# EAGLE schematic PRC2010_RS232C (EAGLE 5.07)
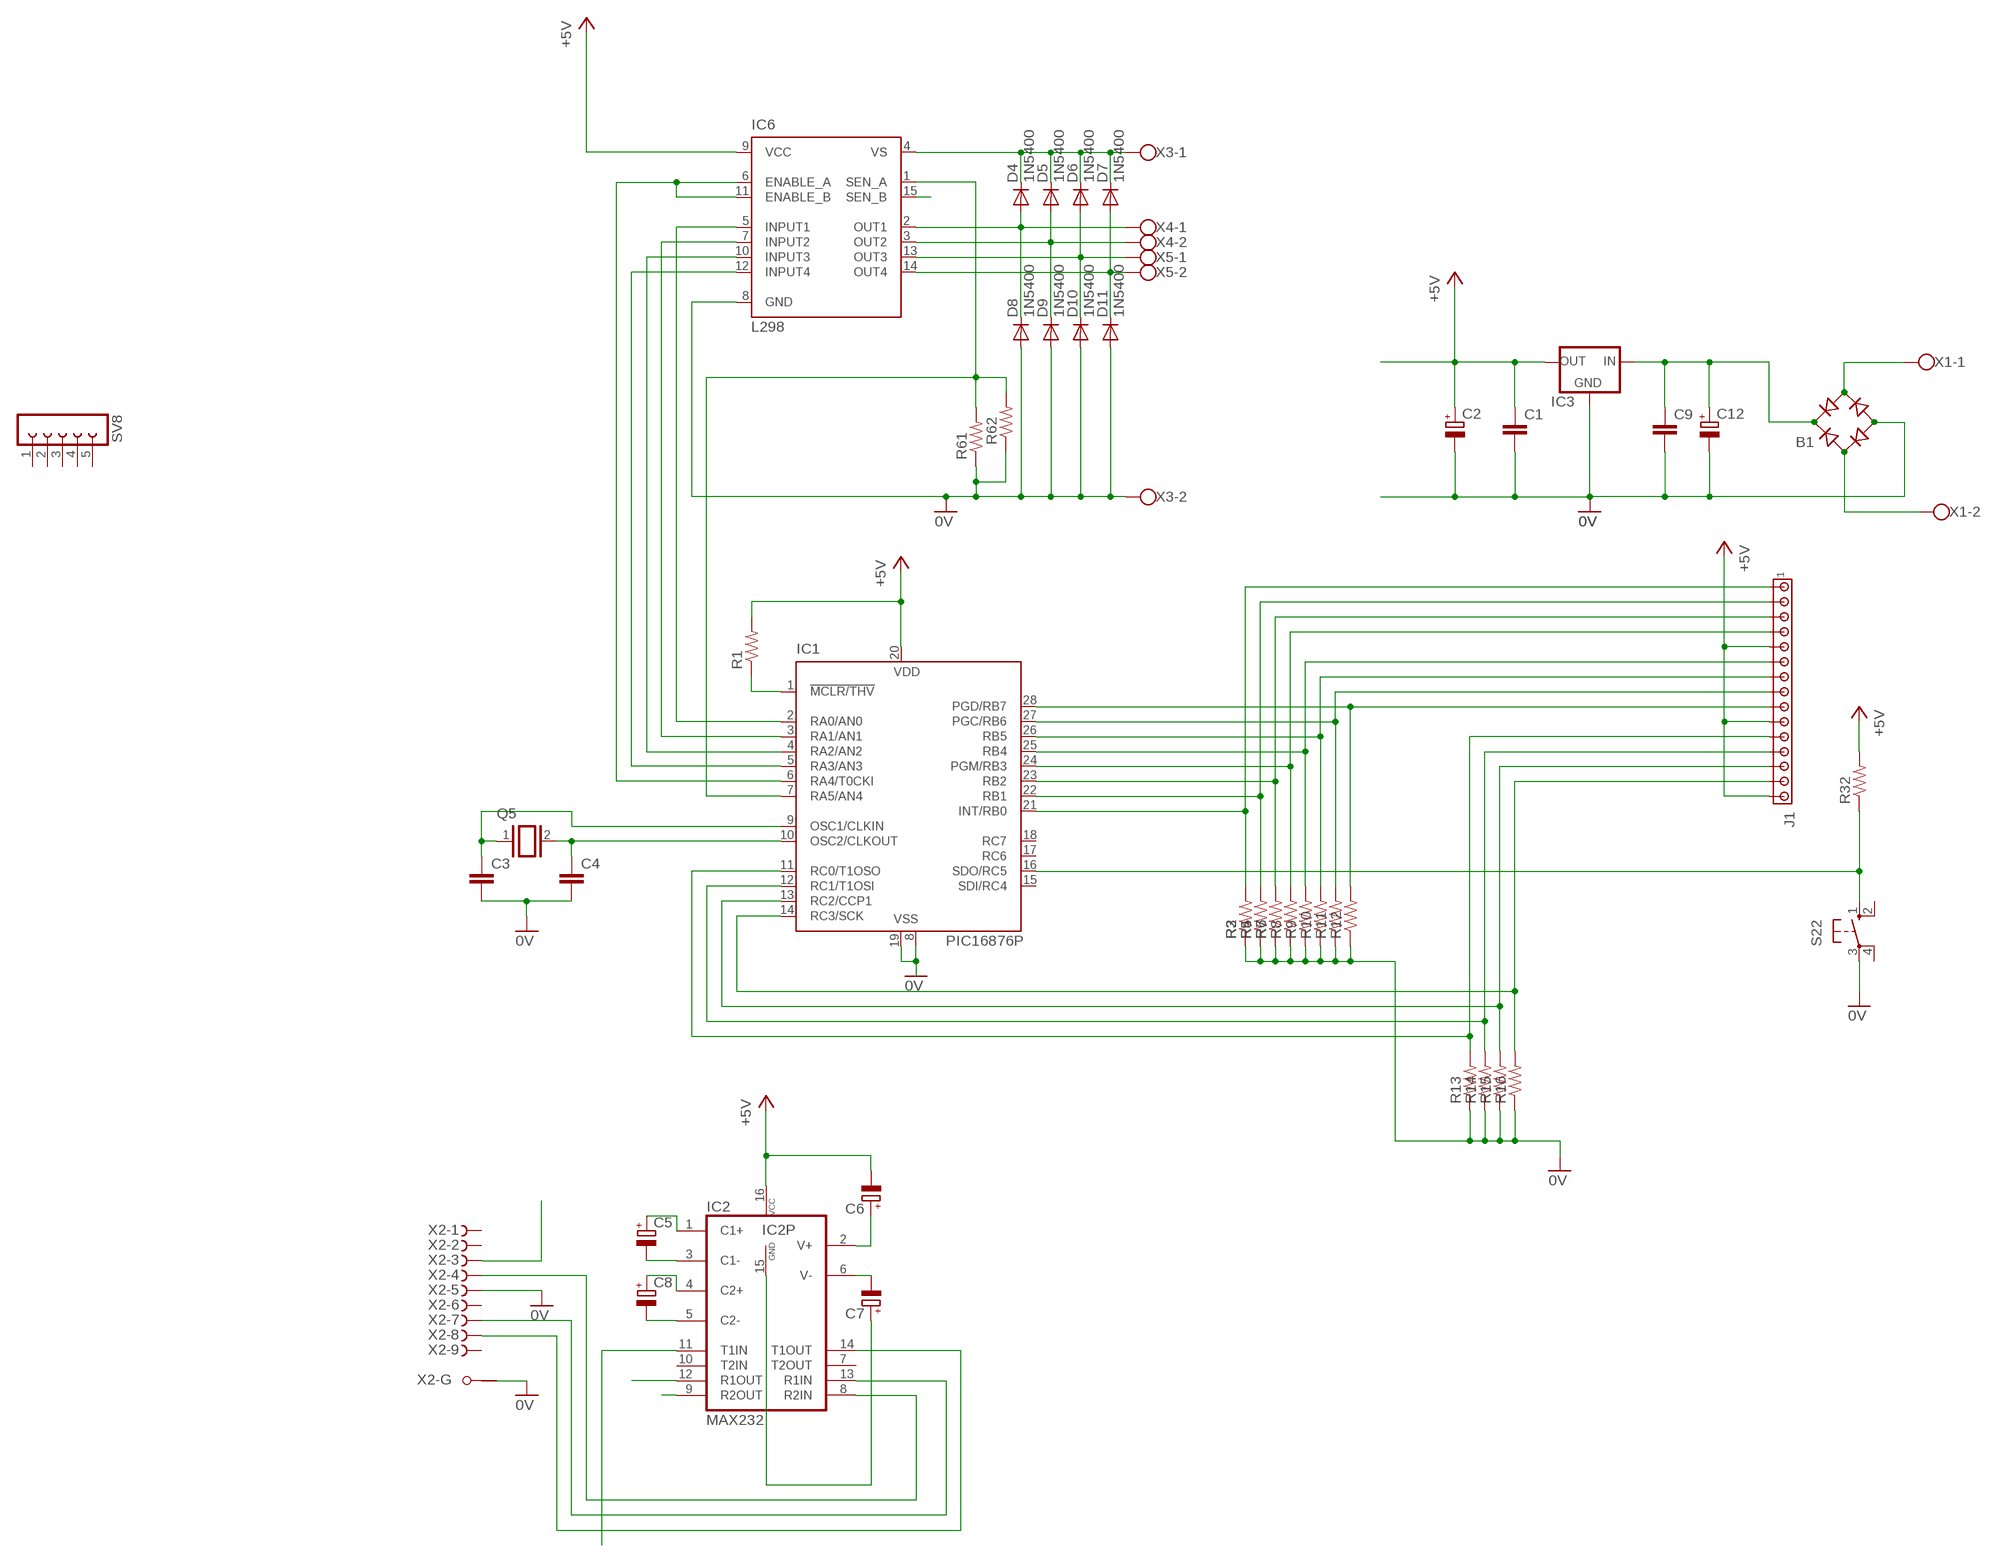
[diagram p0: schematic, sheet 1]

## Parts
B1  RB1A  [RB1A]
C1  C-EU050-025X075  [C050-025X075]
C2  CPOL-EUE2.5-5  [E2,5-5]
C3  C2.5/2  [C2.5-2]
C4  C2.5/2  [C2.5-2]
C5  CPOL-EUE2.5-5  [E2,5-5]
C6  CPOL-EUE2.5-5  [E2,5-5]
C7  CPOL-EUE2.5-5  [E2,5-5]
C8  CPOL-EUE2.5-5  [E2,5-5]
C9  C-EU050-025X075  [C050-025X075]
C12  CPOL-EUE2.5-5  [E2,5-5]
D4  1N5400  [DO201-15]
D5  1N5400  [DO201-15]
D6  1N5400  [DO201-15]
D7  1N5400  [DO201-15]
D8  1N5400  [DO201-15]
D9  1N5400  [DO201-15]
D10  1N5400  [DO201-15]
D11  1N5400  [DO201-15]
IC1  PIC16876P  [DIL28-3]
IC2  MAX232  [DIL16]
IC3  78XXS  [78XXS]
IC6  L298  [MULTIWATT-15]
J1  MTA15-156  [1X15MTA]
Q5  XTAL/S  [QS]
R1  R-US_0207/10  [0207/10]
R2  R-US_0207/10  [0207/10]
R3  R-US_0207/10  [0207/10]
R4  R-US_0207/10  [0207/10]
R5  R-US_0207/10  [0207/10]
R6  R-US_0207/10  [0207/10]
R7  R-US_0207/10  [0207/10]
R8  R-US_0207/10  [0207/10]
R9  R-US_0207/10  [0207/10]
R10  R-US_0207/10  [0207/10]
R11  R-US_0207/10  [0207/10]
R12  R-US_0207/10  [0207/10]
R13  R-US_0207/10  [0207/10]
R14  R-US_0207/10  [0207/10]
R15  R-US_0207/10  [0207/10]
R16  R-US_0207/10  [0207/10]
R32  R-US_0207/10  [0207/10]
R61  R-US_0207/10  [0207/10]
R62  R-US_0207/10  [0207/10]
S22  10-XX  [B3F-10XX]
SV8  FE05-1  [FE05-1]
X1  W237-102  [W237-102]
X2  F09HPS  [F09HP]
X3  W237-102  [W237-102]
X4  W237-102  [W237-102]
X5  W237-102  [W237-102]

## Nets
0V: B1.- C1.2 C2.- C3.2 C4.2 C9.2 C12.- D8.A D9.A D10.A D11.A IC1.8(VSS) IC1.19(VSS) IC3.GND IC6.8(GND) R2.1 R3.1 R4.1 R5.1 R6.1 R7.1 R8.1 R9.1 R10.1 R11.1 R12.1 R13.1 R14.1 R15.1 R16.1 R61.1 R62.1 S22.3(P) X2.5(-5:F) X2.G1(-G:G1) X3.2
+5V: C1.1 C2.+ C6.- IC1.20(VDD) IC2.16(VCC) IC3.OUT IC6.9(VCC) J1.5 J1.10 J1.15 R1.2 R32.2
N$1: C7.+ IC2.15(GND)
N$2: IC6.15(SEN_B)
N$3: IC1.1(!MCLR/THV) R1.1
N$4: IC1.16(SDO/RC5) R32.1 S22.1(S)
N$7: IC1.21(INT/RB0) J1.1 R2.2 R3.2
N$8: IC1.22(RB1) J1.2 R4.2 R5.2
N$10: IC1.24(PGM/RB3) J1.4 R8.2
N$11: IC1.25(RB4) J1.6 R9.2
N$12: IC1.26(RB5) J1.7 R10.2
N$13: IC1.27(PGC/RB6) J1.8 R11.2
N$14: IC1.28(PGD/RB7) J1.9 R12.2
N$15: IC1.11(RC0/T1OSO) J1.11 R13.2
N$16: IC1.12(RC1/T1OSI) J1.12 R14.2
N$17: IC1.13(RC2/CCP1) J1.13 R15.2
N$18: IC1.14(RC3/SCK) J1.14 R16.2
N$23: IC1.23(RB2) J1.3 R6.2 R7.2
N$26: C3.1 IC1.9(OSC1/CLKIN) Q5.1
N$35: IC2.11(T1IN)
N$45: C4.1 IC1.10(OSC2/CLKOUT) Q5.2
N$130: C6.+ IC2.2(V+)
N$131: C5.+ IC2.1(C1+)
N$132: C5.- IC2.3(C1-)
N$133: C7.- IC2.6(V-)
N$134: C8.+ IC2.4(C2+)
N$135: C8.- IC2.5(C2-)
N$136: IC2.13(R1IN) X2.7(-7:F)
N$137: IC2.14(T1OUT) X2.8(-8:F)
N$138: IC2.8(R2IN) X2.4(-4:F)
N$139: X2.3(-3:F)
N$146: IC2.9(R2OUT)
N$147: B1.+ C9.1 C12.+ IC3.IN
N$150: IC2.12(R1OUT)
N$179: IC1.6(RA4/T0CKI) IC6.6(ENABLE_A) IC6.11(ENABLE_B)
N$197: D4.A D8.C IC6.2(OUT1) X4.1
N$198: D5.A D9.C IC6.3(OUT2) X4.2
N$199: D6.A D10.C IC6.13(OUT3) X5.1
N$200: D7.A D11.C IC6.14(OUT4) X5.2
N$201: D4.C D5.C D6.C D7.C IC6.4(VS) X3.1
N$202: IC1.7(RA5/AN4) IC6.1(SEN_A) R61.2 R62.2
N$208: IC1.5(RA3/AN3) IC6.12(INPUT4)
N$209: IC1.4(RA2/AN2) IC6.10(INPUT3)
N$210: IC1.3(RA1/AN1) IC6.7(INPUT2)
N$211: IC1.2(RA0/AN0) IC6.5(INPUT1)
N$231: B1.AC2 X1.1
N$232: B1.AC1 X1.2
Unconnected: IC1.15(SDI/RC4) IC1.17(RC6) IC1.18(RC7) IC2.7(T2OUT) IC2.10(T2IN) S22.2(S1) S22.4(P1) SV8.1 SV8.2 SV8.3 SV8.4 SV8.5 X2.1(-1:F) X2.2(-2:F) X2.6(-6:F) X2.9(-9:F) X2.G2(-G:G2)

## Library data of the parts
B1 = rectifier:RB1A: RECTIFIER 1 A
C1 C9 = resistor:C-EU: CAPACITOR, European symbol
C2 C5-C8 C12 = resistor:CPOL-EU: POLARIZED CAPACITOR, European symbol
C3 C4 = capacitor-wima:C: CAPACITOR
D4-D11 = diode:1N5400: DIODE
IC1 = microchip:PIC16*876: MICROCONTROLLER flash type
IC2 = maxim:MAX232: RS232 TRANSEIVER
IC3 = v-reg:78XXS: VOLTAGE REGULATOR
IC6 = st-microelectronics:L298: DUAL FULL-BRIDGE DRIVER
J1 = con-amp:MTA15-156: AMP connector
Q5 = special:XTAL/S: CRYSTAL
R1-R16 R32 R61 R62 = resistor:R-US_: RESISTOR, American symbol
S22 = switch-omron:10-XX: OMRON SWITCH
SV8 = con-lsta:FE05-1: FEMALE HEADER
X1 X3-X5 = con-wago-500:W237-102: WAGO SCREW CLAMP
X2 = con-subd:F09HPS: SUB-D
